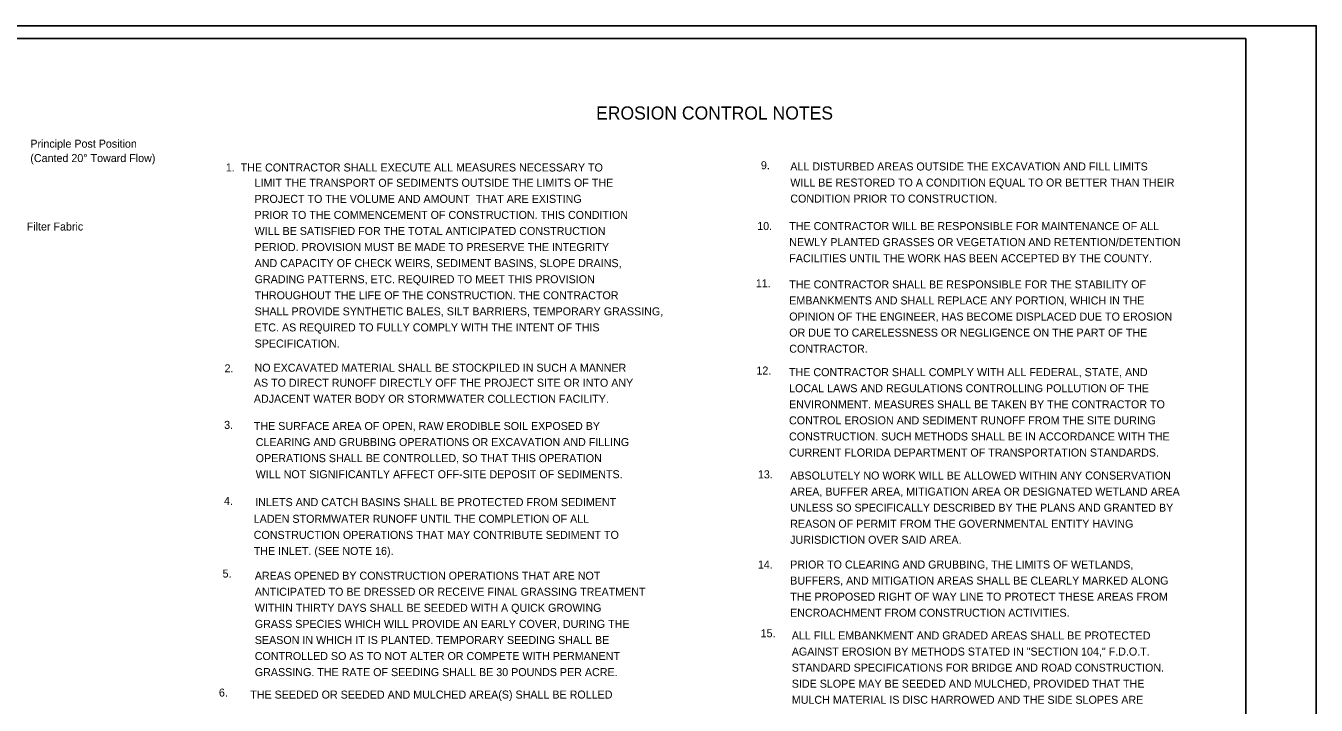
# Model space of a CAD drawing. Extents: x 539344 to 540004, y 1574686 to 1575110.
# Drawn here: x 539600.9 to 540004, y 1574898.2 to 1575110.5 of the extents above; entities that cross this region are included whole.
import ezdxf

# ---------------------------------------------------------------- set-up
doc = ezdxf.new("R2010")
doc.units = 0
for name, color, linetype in [('Default', 7, 'Continuous'), ('PlotBorder_dp', 7, 'Continuous'), ('SheetBorder_dp', 7, 'Continuous')]:
    doc.layers.add(name, color=color, linetype=linetype)

msp = doc.modelspace()

# ---------------------------------------------------------------- linework, layer by layer
at = {"layer": 'PlotBorder_dp'}
msp.add_lwpolyline([(539343.95, 1574686.45), (540003.95, 1574686.45), (540003.95, 1575110.45), (539343.95, 1575110.45)], close=True, dxfattribs=at)
at = {"layer": 'SheetBorder_dp'}
for p, q in [((539365.95, 1575106.45), (539981.95, 1575106.45)), ((539981.95, 1575106.45), (539981.95, 1574690.45))]:
    msp.add_line(p, q, dxfattribs=at)

# ---------------------------------------------------------------- texts
at = {"layer": 'Default'}
for s, height, p in [('EROSION CONTROL NOTES ', 4.0991, (539779.03, 1575081.17)), ('Principle Post Position', 2.5, (539602.33, 1575072.39)), ('(Canted 20° Toward Flow)', 2.5, (539602.33, 1575067.89)), ('1.  THE CONTRACTOR SHALL EXECUTE ALL MEASURES NECESSARY TO', 2.5, (539663.39, 1575064.95)), ('9.', 2.5, (539830.51, 1575065.65)), ('ALL DISTURBED AREAS OUTSIDE THE EXCAVATION AND FILL LIMITS ', 2.5, (539839.7, 1575065.27)), ('LIMIT THE TRANSPORT OF SEDIMENTS OUTSIDE THE LIMITS OF THE', 2.5, (539672.38, 1575060.16)), ('WILL BE RESTORED TO A CONDITION EQUAL TO OR BETTER THAN THEIR', 2.5, (539839.7, 1575060.25)), ('PROJECT TO THE VOLUME AND AMOUNT  THAT ARE EXISTING ', 2.5, (539672.38, 1575055.15)), ('CONDITION PRIOR TO CONSTRUCTION.', 2.5, (539839.7, 1575055.23)), ('PRIOR TO THE COMMENCEMENT OF CONSTRUCTION. THIS CONDITION', 2.5, (539672.38, 1575050.13)), ('Filter Fabric', 2.5, (539601.2, 1575046.51)), ('10.', 2.5, (539829.36, 1575046.67)), ('THE CONTRACTOR WILL BE RESPONSIBLE FOR MAINTENANCE OF ALL', 2.5, (539839.37, 1575046.65)), ('WILL BE SATISFIED FOR THE TOTAL ANTICIPATED CONSTRUCTION', 2.5, (539672.38, 1575045.11)), ('NEWLY PLANTED GRASSES OR VEGETATION AND RETENTION/DETENTION', 2.5, (539839.37, 1575041.63)), ('PERIOD. PROVISION MUST BE MADE TO PRESERVE THE INTEGRITY', 2.5, (539672.38, 1575040.09)), ('AND CAPACITY OF CHECK WEIRS, SEDIMENT BASINS, SLOPE DRAINS,', 2.5, (539672.38, 1575035.07)), ('FACILITIES UNTIL THE WORK HAS BEEN ACCEPTED BY THE COUNTY.', 2.5, (539839.37, 1575036.61)), ('GRADING PATTERNS, ETC. REQUIRED TO MEET THIS PROVISION ', 2.5, (539672.38, 1575030.05)), ('11.', 2.5, (539828.93, 1575028.78)), ('THE CONTRACTOR SHALL BE RESPONSIBLE FOR THE STABILITY OF', 2.5, (539839.37, 1575028.43)), ('THROUGHOUT THE LIFE OF THE CONSTRUCTION. THE CONTRACTOR', 2.5, (539672.38, 1575025.03)), ('EMBANKMENTS AND SHALL REPLACE ANY PORTION, WHICH IN THE ', 2.5, (539839.37, 1575023.41)), ('SHALL PROVIDE SYNTHETIC BALES, SILT BARRIERS, TEMPORARY GRASSING,', 2.5, (539672.38, 1575020.01)), ('OPINION OF THE ENGINEER, HAS BECOME DISPLACED DUE TO EROSION', 2.5, (539839.37, 1575018.39)), ('ETC. AS REQUIRED TO FULLY COMPLY WITH THE INTENT OF THIS', 2.5, (539672.38, 1575014.99)), ('OR DUE TO CARELESSNESS OR NEGLIGENCE ON THE PART OF THE', 2.5, (539839.37, 1575013.37)), ('SPECIFICATION.', 2.5, (539672.38, 1575009.97)), ('CONTRACTOR.', 2.5, (539839.37, 1575008.35)), ('2.', 2.5, (539662.99, 1575002.22)), ('NO EXCAVATED MATERIAL SHALL BE STOCKPILED IN SUCH A MANNER', 2.5, (539672.35, 1575002.4)), ('12.', 2.5, (539829.11, 1575001.53)), ('AS TO DIRECT RUNOFF DIRECTLY OFF THE PROJECT SITE OR INTO ANY', 2.5, (539672.14, 1574997.72)), ('THE CONTRACTOR SHALL COMPLY WITH ALL FEDERAL, STATE, AND', 2.5, (539839.3, 1575001.02)), ('LOCAL LAWS AND REGULATIONS CONTROLLING POLLUTION OF THE ', 2.5, (539839.3, 1574996)), ('ADJACENT WATER BODY OR STORMWATER COLLECTION FACILITY.', 2.5, (539672.14, 1574992.7)), ('ENVIRONMENT. MEASURES SHALL BE TAKEN BY THE CONTRACTOR TO ', 2.5, (539839.3, 1574990.98)), ('CONTROL EROSION AND SEDIMENT RUNOFF FROM THE SITE DURING', 2.5, (539839.3, 1574985.96)), ('3.', 2.5, (539662.87, 1574984.55)), ('THE SURFACE AREA OF OPEN, RAW ERODIBLE SOIL EXPOSED BY', 2.5, (539672.14, 1574984.2)), ('CLEARING AND GRUBBING OPERATIONS OR EXCAVATION AND FILLING', 2.5, (539672.72, 1574979.18)), ('CONSTRUCTION. SUCH METHODS SHALL BE IN ACCORDANCE WITH THE', 2.5, (539839.3, 1574980.94)), ('OPERATIONS SHALL BE CONTROLLED, SO THAT THIS OPERATION', 2.5, (539672.72, 1574974.16)), ('CURRENT FLORIDA DEPARTMENT OF TRANSPORTATION STANDARDS.', 2.5, (539839.3, 1574975.92)), ('WILL NOT SIGNIFICANTLY AFFECT OFF-SITE DEPOSIT OF SEDIMENTS.', 2.5, (539672.72, 1574969.14)), ('13.', 2.5, (539829.57, 1574969.09)), ('ABSOLUTELY NO WORK WILL BE ALLOWED WITHIN ANY CONSERVATION', 2.5, (539839.67, 1574968.74)), ('AREA, BUFFER AREA, MITIGATION AREA OR DESIGNATED WETLAND AREA', 2.5, (539839.67, 1574963.72)), ('4.', 2.5, (539662.81, 1574960.81)), ('INLETS AND CATCH BASINS SHALL BE PROTECTED FROM SEDIMENT ', 2.5, (539672.57, 1574960.42)), ('UNLESS SO SPECIFICALLY DESCRIBED BY THE PLANS AND GRANTED BY', 2.5, (539839.67, 1574958.7)), ('LADEN STORMWATER RUNOFF UNTIL THE COMPLETION OF ALL', 2.5, (539672.11, 1574955.21)), ('REASON OF PERMIT FROM THE GOVERNMENTAL ENTITY HAVING ', 2.5, (539839.67, 1574953.68)), ('CONSTRUCTION OPERATIONS THAT MAY CONTRIBUTE SEDIMENT TO', 2.5, (539672.11, 1574950.19)), ('THE INLET. (SEE NOTE 16).', 2.5, (539672.11, 1574945.17)), ('JURISDICTION OVER SAID AREA.', 2.5, (539839.67, 1574948.66)), ('14.', 2.5, (539829.57, 1574940.94)), ('PRIOR TO CLEARING AND GRUBBING, THE LIMITS OF WETLANDS, ', 2.5, (539839.67, 1574940.94)), ('5.', 2.5, (539662.38, 1574938.12)), ('AREAS OPENED BY CONSTRUCTION OPERATIONS THAT ARE NOT ', 2.5, (539672.44, 1574937.45)), ('BUFFERS, AND MITIGATION AREAS SHALL BE CLEARLY MARKED ALONG', 2.5, (539839.67, 1574935.92)), ('ANTICIPATED TO BE DRESSED OR RECEIVE FINAL GRASSING TREATMENT', 2.5, (539672.44, 1574932.43)), ('THE PROPOSED RIGHT OF WAY LINE TO PROTECT THESE AREAS FROM', 2.5, (539839.67, 1574930.9)), ('WITHIN THIRTY DAYS SHALL BE SEEDED WITH A QUICK GROWING', 2.5, (539672.44, 1574927.41)), ('ENCROACHMENT FROM CONSTRUCTION ACTIVITIES.', 2.5, (539839.62, 1574925.88)), ('GRASS SPECIES WHICH WILL PROVIDE AN EARLY COVER, DURING THE', 2.5, (539672.44, 1574922.39)), ('SEASON IN WHICH IT IS PLANTED. TEMPORARY SEEDING SHALL BE', 2.5, (539672.44, 1574917.37)), ('15.', 2.5, (539830.43, 1574919.46)), ('ALL FILL EMBANKMENT AND GRADED AREAS SHALL BE PROTECTED ', 2.5, (539840.16, 1574918.77)), ('AGAINST EROSION BY METHODS STATED IN "SECTION 104," F.D.O.T.', 2.5, (539840.16, 1574913.75)), ('CONTROLLED SO AS TO NOT ALTER OR COMPETE WITH PERMANENT ', 2.5, (539672.44, 1574912.35)), ('STANDARD SPECIFICATIONS FOR BRIDGE AND ROAD CONSTRUCTION.', 2.5, (539840.16, 1574908.73)), ('GRASSING. THE RATE OF SEEDING SHALL BE 30 POUNDS PER ACRE.', 2.5, (539672.44, 1574907.33)), ('6.', 2.5, (539661.23, 1574900.94)), ('SIDE SLOPE MAY BE SEEDED AND MULCHED, PROVIDED THAT THE ', 2.5, (539840.16, 1574903.71)), ('THE SEEDED OR SEEDED AND MULCHED AREA(S) SHALL BE ROLLED ', 2.5, (539671.02, 1574900.31)), ('MULCH MATERIAL IS DISC HARROWED AND THE SIDE SLOPES ARE ', 2.5, (539840.16, 1574898.69))]:
    msp.add_text(s, height=height, dxfattribs=at).set_placement(p)

doc.saveas('drawing.dxf')
